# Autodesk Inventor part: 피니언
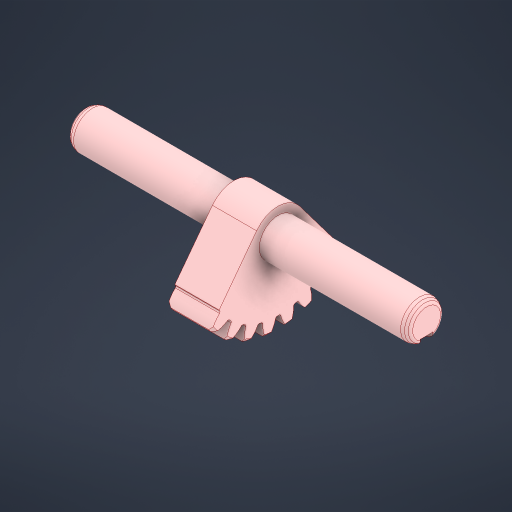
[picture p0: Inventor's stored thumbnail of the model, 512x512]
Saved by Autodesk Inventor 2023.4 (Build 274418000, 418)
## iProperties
Created: 2024-05
Part Number: 피니언
Material: 강철, 탄소
Document SubType Name: Modeling
Designer: Edu03
Density: 7.85 g/cm^3
Appearance: 기본값
Sending System: Autodesk Inventor 2025
Preprocessor: ST-DEVELOPER v20
Author: jhkim
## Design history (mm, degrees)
node "피니언1"
node "솔리드2"
node "솔리드1"
